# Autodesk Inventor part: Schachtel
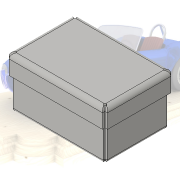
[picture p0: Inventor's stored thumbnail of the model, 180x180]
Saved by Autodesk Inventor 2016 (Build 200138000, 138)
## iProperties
Created: 2015-05
Part Number: Schachtel
Material: Generic
Document SubType Name: Sheet Metal
Designer: thomas
Density: 1 g/cm^3
Sheet Metal Rule: Standard_mm
Appearance: Default
Author: thomas
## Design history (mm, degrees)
sketch "Skizze1"
  geometry: L1 (62.5, -42.5)-(-62.5, -42.5); L2 (-62.5, -42.5)-(-62.5, 42.5); L3 (-62.5, 42.5)-(62.5, 42.5); L4 (62.5, 42.5)-(62.5, -42.5); L5 (62.5, -42.5)-(-62.5, 42.5); L6 (-62.5, -42.5)-(62.5, 42.5); 1 further point
  constraints: 12 end point, 2 midpoint, 2 parallel, 1 horizontal, 1 perpendicular
  dimensions: "d0" = 125 distance of L2.end L3.end; "d1" = 85 distance of L1.end L2.end
workplane "Arbeitsebene1"
sketch "Skizze2"
  geometry: L1 (-62.5, -42.5)-(-62.5, 42.5) reference; L2 (-62.5, 42.5)-(62.5, 42.5) reference; L3 (62.5, 42.5)-(62.5, -42.5) reference; L4 (62.5, -42.5)-(-62.5, -42.5) reference; L5 (65.5, 45.5)-(-65.5, 45.5); L6 (-65.5, 45.5)-(-65.5, -45.5); L7 (-65.5, -45.5)-(65.5, -45.5); L8 (65.5, -45.5)-(65.5, 45.5); 1 further point
  constraints: 8 end point, 3 other
  dimensions: "d3" = 3 distance between parallel lines of L5 L2
node "Fläche1"
node "Fläche2"
node "Lasche1"
node "Lasche2"
feature "Verdickung1" dims "d30" = 1, "d31" = 1
node "Volumenkörper1"
feature "Grobblech1" dims "Thickness" = 2 (derived)
feature "Grobblech2" dims "Thickness" = 2 (derived)
sketch "Skizze3"
  geometry: L1 through (-42.5, 0) direction (1, 0); L2 through (0, 27.5) direction (0, 1); L3 (0, 55)-(-85, 55); L4 (-85, 55)-(-85, 0)
  constraints: 6 end point, 1 horizontal, 1 perpendicular, 1 vertical
feature "Grobblech3" dims "d10" = 2 (= BendReliefWidth), "d11" = 1 (= BendReliefDepth), "d12" = 4 (= MinimumRemnant), "d13" = 2 (= BendRadius), "d14" = 55 (computed from m_height), "d15" = 90 deg, "d16" = 2 (= BendRadius), "d17" = 8 (= CornerReliefSize), "d18" = 1 (= GapSize), "d19" = 2 (= JacobiRadiusSize), "SeamGap" = 0.01, "Thickness" = 2 (derived)
feature "Biegung2" dims "d10" = 2 (= BendReliefWidth), "d11" = 1 (= BendReliefDepth), "d12" = 4 (= MinimumRemnant), "d13" = 2 (= BendRadius), "d14" = 55 (computed from m_height), "d15" = 90 deg, "d16" = 2 (= BendRadius), "SeamGap" = 0.01, "Thickness" = 2 (derived)
feature "Ecke1" dims "d14" = 55 (computed from m_height), "d15" = 90 deg, "d17" = 8 (= CornerReliefSize), "d18" = 1 (= GapSize), "d19" = 2 (= JacobiRadiusSize)
sketch "Skizze4"
  geometry: L1 through (65.5, 0) direction (-1, 0); L2 through (0, -12.5) direction (0, -1); L3 (0, -25)-(131, -25); L4 (131, -25)-(131, 0)
  constraints: 6 end point, 1 horizontal, 1 perpendicular, 1 vertical
feature "Grobblech4" dims "d20" = 2 (= BendReliefWidth), "d21" = 1 (= BendReliefDepth), "d22" = 4 (= MinimumRemnant), "d23" = 2 (= BendRadius), "d24" = 25, "d25" = 90 deg, "d26" = 4 (= 2 x BendRadius), "d27" = 8 (= CornerReliefSize), "d28" = 2 (= 2 x GapSize), "d29" = 2 (= JacobiRadiusSize), "SeamGap" = 0.01, "Thickness" = 2 (derived)
feature "Biegung3" dims "d20" = 2 (= BendReliefWidth), "d21" = 1 (= BendReliefDepth), "d22" = 4 (= MinimumRemnant), "d23" = 2 (= BendRadius), "d24" = 25, "d25" = 90 deg, "d26" = 4 (= 2 x BendRadius), "SeamGap" = 0.01, "Thickness" = 2 (derived)
feature "Ecke2" dims "d24" = 25, "d25" = 90 deg, "d27" = 8 (= CornerReliefSize), "d28" = 2 (= 2 x GapSize), "d29" = 2 (= JacobiRadiusSize)
node "Volumenkörper2"
other parameters: "BendRadius" = 2 (= Thickness), "BendReliefWidth" = 2 (= Thickness), "BendReliefDepth" = 1 (= 0.5 x Thickness), "CornerReliefSize" = 8 (= 4 x Thickness), "MinimumRemnant" = 4 (= 2 x Thickness), "TransitionRadius" = 2 (= BendRadius), "JacobiRadiusSize" = 2 (= BendRadius), "GapSize" = 1 (= 0.5 x Thickness), "m_height" = 65, "d4" = 2 (= BendRadius)
